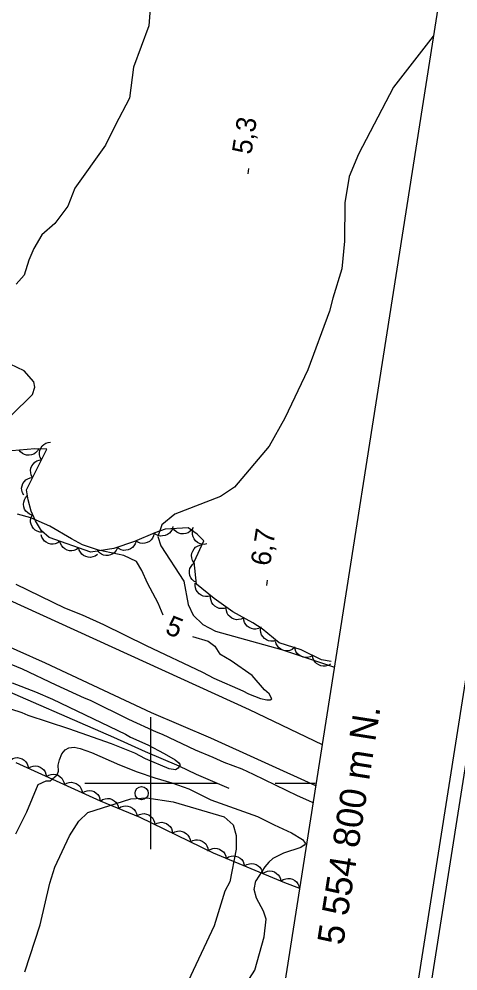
# Model space of a CAD drawing. Extents: x 282461 to 284471, y 5554090 to 5557646.
# Drawn here: x 283980 to 284046.6, y 5554771.5 to 5554915.8 of the extents above; entities that cross this region are included whole.
import ezdxf

# ---------------------------------------------------------------- set-up
doc = ezdxf.new("R2010")
doc.units = 0
for name, color, linetype in [('Niveau 1', 7, 'Continuous'), ('Niveau 2', 7, 'Continuous'), ('Niveau 21', 7, 'Continuous'), ('Niveau 3', 7, 'Continuous'), ('Niveau 36', 7, 'Continuous'), ('Niveau 4', 7, 'Continuous'), ('Niveau 44', 7, 'Continuous'), ('Niveau 60', 7, 'Continuous'), ('Niveau 61', 7, 'Continuous')]:
    doc.layers.add(name, color=color, linetype=linetype)

msp = doc.modelspace()

# ---------------------------------------------------------------- linework, layer by layer
at = {"layer": 'Niveau 1'}
for points in [[(283978.86, 5554855.69), (283982.06, 5554858.86), (283982.41, 5554859.99), (283982.3, 5554860.78), (283980.83, 5554862.48), (283978.67, 5554863.5)], [(284001.9, 5554825.45), (284001.11, 5554827.26), (283999.53, 5554830.31), (283998.63, 5554832.24), (283997.85, 5554833.6), (283995.92, 5554834.51), (283992.06, 5554835.3), (283989.67, 5554836.09), (283987.97, 5554837), (283984.69, 5554838.93), (283981.85, 5554840.18), (283979.81, 5554840.74)], [(283979.55, 5554830.13), (283986.92, 5554826.56), (283989.59, 5554825.48), (283992.82, 5554824.01), (283999.29, 5554820.83), (284007.85, 5554816.81), (284009.55, 5554815.9), (284013.97, 5554813.98), (284014.82, 5554813.52), (284016.63, 5554812.84), (284017.6, 5554812.62), (284018.11, 5554812.62), (284018.34, 5554812.79), (284017.95, 5554813.52), (284017.27, 5554814.15), (284015.4, 5554816.3)], [(284006.32, 5554822.23), (284008.71, 5554821.49), (284009.74, 5554820.74), (284010.48, 5554819.53)], [(284015.4, 5554816.3), (284012.18, 5554818.51), (284010.48, 5554819.53)], [(283978.81, 5554818.01), (283980.51, 5554817.33), (283985.61, 5554814.89), (283989.92, 5554812.91), (283990.83, 5554812.57), (283996.61, 5554809.68), (284000.81, 5554807.76), (284001.72, 5554807.42), (284006.76, 5554805.04), (284009.43, 5554803.96), (284011.07, 5554803.17), (284013.79, 5554802.15), (284015.55, 5554801.36), (284022.18, 5554798.13), (284023.94, 5554797.39), (284024.59, 5554797.05)], [(283985.82, 5554801.25), (283986, 5554801.82), (283985.95, 5554802.72), (283986.18, 5554803.51), (283986.52, 5554804.42), (283987.04, 5554805.04), (283987.61, 5554805.33), (283988.4, 5554805.44), (283989.31, 5554805.27), (283991.02, 5554804.65), (283995.27, 5554802.78), (283997.93, 5554801.7), (284000.6, 5554800.79), (284003.21, 5554800.06), (284005.77, 5554799.15), (284009.11, 5554797.45), (284016.2, 5554794.96), (284018.69, 5554793.66), (284021.36, 5554792.47), (284023, 5554791.45), (284023.45, 5554790.88), (284023.28, 5554790.6), (284022.77, 5554790.26), (284020.15, 5554789.41), (284018.5, 5554788.56), (284017.93, 5554788.05), (284017.3, 5554787.32), (284015.92, 5554785.22)], [(283979.53, 5554792.3), (283981.24, 5554795.64), (283982.92, 5554799.81), (283984.17, 5554800.35), (283984.74, 5554800.35), (283985.82, 5554801.25)], [(284014.17, 5554769.14), (284015.76, 5554771.65), (284017.2, 5554776.72), (284017.48, 5554779.41), (284017.09, 5554780.58), (284016.02, 5554782.56), (284015.69, 5554783.87), (284015.92, 5554785.22)]]:
    msp.add_lwpolyline(points, dxfattribs=at)
at = {"layer": 'Niveau 2'}
for points in [[(284000.07, 5554919.32), (283999.7, 5554914.76), (283997.37, 5554908.47), (283996.78, 5554903.76), (283994.61, 5554899.65), (283993.14, 5554896.66), (283988.51, 5554890.13), (283987.42, 5554887.42), (283985.48, 5554884.81), (283983.48, 5554883.06), (283982.3, 5554881.02), (283981.51, 5554879.25), (283980.82, 5554876.98), (283979.58, 5554875.62)], [(284042.82, 5554913.19), (284036.81, 5554905.43), (284031.48, 5554895.31), (284030.09, 5554891.93), (284029.45, 5554887.94), (284029.4, 5554882.13), (284028.96, 5554877.9), (284027.59, 5554873.5), (284027.09, 5554871.53), (284023.84, 5554862.6), (284020.31, 5554855.28), (284017.95, 5554851.06), (284012.68, 5554844.83), (284010.57, 5554843.43), (284003.67, 5554840.74), (284001.7, 5554839.16), (284001.08, 5554837.38), (284001.55, 5554835.93), (284005, 5554830.62), (284005.67, 5554827.09), (284006.44, 5554825.44), (284007.92, 5554824.01), (284009.81, 5554823.04), (284019.82, 5554820.26), (284027.7, 5554817.62)], [(283979.02, 5554815.19), (283982.54, 5554813.83), (283985.09, 5554812.7), (283996.16, 5554807.42), (283996.95, 5554806.97), (283999.56, 5554805.78), (284002.06, 5554804.48), (284003.71, 5554803.51), (284004.27, 5554803.06), (284004.44, 5554802.77), (284004.15, 5554802.27), (284003.75, 5554802.04), (284002.79, 5554802.15), (283999.21, 5554803.68), (283997.57, 5554804.53), (283994.05, 5554805.95), (283987.57, 5554808.22), (283981.44, 5554810.26), (283980.53, 5554810.66), (283978.77, 5554811.23)], [(283980.93, 5554771.4), (283983.24, 5554778.55), (283984.7, 5554784.83), (283985.44, 5554787.27), (283987.71, 5554792.04), (283989.11, 5554794.25), (283990.49, 5554795.56), (283996.96, 5554797.63), (283999.39, 5554797.77), (284003.4, 5554797.16), (284011.12, 5554794.92), (284012.49, 5554793.68), (284012.93, 5554792.07), (284012.94, 5554790.02), (284012, 5554785.05), (284011.26, 5554783.61), (284009.61, 5554778.4), (284005.26, 5554769.15)]]:
    msp.add_lwpolyline(points, dxfattribs=at)
at = {"layer": 'Niveau 21'}
for points in [[(283896.54, 5554865.24), (283906.59, 5554860.53), (283913.91, 5554857.24), (283921.63, 5554853.44), (283936.73, 5554846.7), (283965.15, 5554833.84), (284014.91, 5554811.14), (284025.97, 5554805.86)], [(283894.01, 5554859.02), (283904.79, 5554853.98), (283912.17, 5554850.4), (283922.9, 5554845.36), (283944.86, 5554835.61), (283957.34, 5554830.35), (283975.37, 5554822.08), (283983.99, 5554818.23), (284000.08, 5554810.69), (284009.04, 5554806.84), (284024.99, 5554799.62)]]:
    msp.add_lwpolyline(points, dxfattribs=at)
at = {"layer": 'Niveau 3'}
for p, q in [((284014.77, 5554892.31), (284014.89, 5554893.1)), ((284017.6, 5554829.95), (284017.72, 5554830.74))]:
    msp.add_line(p, q, dxfattribs=at)
at = {"layer": 'Niveau 36'}
msp.add_circle((283998.62, 5554798.47), 1, dxfattribs=at)
at = {"layer": 'Niveau 4'}
msp.add_lwpolyline([(284011.88, 5554799.19), (284006.96, 5554801.33), (284004.33, 5554802.58), (283999.23, 5554804.74), (283994.41, 5554806.94), (283975.11, 5554815.3), (283970.63, 5554817.46), (283966.48, 5554819.28), (283961.71, 5554821.77), (283949.61, 5554827.73), (283940.34, 5554830.8), (283934.37, 5554832.66), (283930.62, 5554833.73), (283928.8, 5554834.06), (283926.46, 5554833.89), (283925.09, 5554833.7)], dxfattribs=at)
at = {"layer": 'Niveau 44'}
for points in [[(284027.38, 5554818.45), (284025.9, 5554818.69), (284022.8, 5554820.2), (284019.46, 5554821.28), (284016.88, 5554823.37), (284015.48, 5554824.29), (284012.45, 5554825.93), (284009.61, 5554827.99), (284006.94, 5554830.15), (284006.59, 5554833.53), (284008.06, 5554836.7), (284007.06, 5554837.71), (284005.69, 5554838.7), (284002.18, 5554838.46), (284000.62, 5554837.94), (283997.55, 5554836.61), (283994.42, 5554835.55), (283990.93, 5554835), (283984.62, 5554837.21), (283983.45, 5554838.25), (283982.53, 5554839.74), (283981.87, 5554841.22), (283981.42, 5554842.91), (283981.15, 5554844.42), (283984.25, 5554850.59), (283982.43, 5554850.65), (283978.93, 5554850.37)], [(283983.04, 5554850.7), (283982.83, 5554850.33), (283982.54, 5554850.05), (283982.27, 5554849.86), (283981.94, 5554849.74), (283981.57, 5554849.68), (283981.19, 5554849.71), (283980.87, 5554849.78), (283980.56, 5554849.95), (283980.26, 5554850.18), (283980.04, 5554850.46)], [(283983.44, 5554848.98), (283983.24, 5554849.35), (283983.15, 5554849.75), (283983.12, 5554850.08), (283983.2, 5554850.42), (283983.33, 5554850.77), (283983.56, 5554851.08), (283983.78, 5554851.32), (283984.09, 5554851.49), (283984.44, 5554851.63), (283984.79, 5554851.67)], [(283982.09, 5554846.29), (283981.89, 5554846.66), (283981.8, 5554847.06), (283981.77, 5554847.39), (283981.85, 5554847.73), (283981.98, 5554848.08), (283982.21, 5554848.39), (283982.43, 5554848.63), (283982.74, 5554848.81), (283983.08, 5554848.94), (283983.44, 5554848.98)], [(283980.74, 5554843.61), (283980.54, 5554843.97), (283980.45, 5554844.37), (283980.42, 5554844.7), (283980.49, 5554845.05), (283980.63, 5554845.39), (283980.86, 5554845.7), (283981.08, 5554845.94), (283981.39, 5554846.12), (283981.73, 5554846.25), (283982.09, 5554846.29)], [(283982.03, 5554840.6), (283981.64, 5554840.74), (283981.31, 5554840.98), (283981.07, 5554841.21), (283980.89, 5554841.52), (283980.77, 5554841.87), (283980.73, 5554842.25), (283980.74, 5554842.58), (283980.85, 5554842.91), (283981.02, 5554843.24), (283981.26, 5554843.51)], [(283983.59, 5554838.02), (283983.18, 5554838.03), (283982.79, 5554838.17), (283982.5, 5554838.32), (283982.24, 5554838.56), (283982.02, 5554838.86), (283981.87, 5554839.22), (283981.78, 5554839.53), (283981.79, 5554839.88), (283981.87, 5554840.25), (283982.01, 5554840.58)], [(283986.24, 5554836.64), (283985.9, 5554836.39), (283985.52, 5554836.25), (283985.2, 5554836.19), (283984.85, 5554836.21), (283984.49, 5554836.3), (283984.15, 5554836.49), (283983.88, 5554836.68), (283983.67, 5554836.96), (283983.49, 5554837.29), (283983.4, 5554837.64)], [(284000.52, 5554837.9), (284000.44, 5554837.49), (284000.26, 5554837.12), (284000.06, 5554836.85), (283999.79, 5554836.63), (283999.46, 5554836.46), (283999.09, 5554836.37), (283998.76, 5554836.32), (283998.42, 5554836.38), (283998.07, 5554836.51), (283997.76, 5554836.7)], [(284003.37, 5554838.86), (284003.26, 5554838.45), (284003.04, 5554838.11), (284002.83, 5554837.86), (284002.53, 5554837.66), (284002.19, 5554837.52), (284001.81, 5554837.46), (284001.48, 5554837.44), (284001.14, 5554837.53), (284000.8, 5554837.69), (284000.52, 5554837.91)], [(284006.44, 5554838.75), (284006.23, 5554838.39), (284005.93, 5554838.11), (284005.66, 5554837.92), (284005.32, 5554837.81), (284004.96, 5554837.75), (284004.57, 5554837.79), (284004.25, 5554837.85), (284003.95, 5554838.03), (284003.66, 5554838.26), (284003.43, 5554838.55)], [(284008.51, 5554836.24), (284008.1, 5554836.16), (284007.7, 5554836.21), (284007.38, 5554836.29), (284007.07, 5554836.47), (284006.79, 5554836.71), (284006.57, 5554837.02), (284006.41, 5554837.31), (284006.34, 5554837.65), (284006.33, 5554838.03), (284006.4, 5554838.38)], [(283989.08, 5554835.65), (283988.74, 5554835.4), (283988.36, 5554835.26), (283988.04, 5554835.19), (283987.68, 5554835.22), (283987.33, 5554835.31), (283986.99, 5554835.5), (283986.72, 5554835.68), (283986.51, 5554835.96), (283986.33, 5554836.29), (283986.24, 5554836.64)], [(283997.77, 5554836.68), (283997.66, 5554836.28), (283997.44, 5554835.93), (283997.23, 5554835.68), (283996.93, 5554835.49), (283996.59, 5554835.34), (283996.21, 5554835.28), (283995.89, 5554835.26), (283995.54, 5554835.35), (283995.21, 5554835.5), (283994.92, 5554835.72)], [(283991.92, 5554834.65), (283991.58, 5554834.4), (283991.2, 5554834.27), (283990.88, 5554834.2), (283990.52, 5554834.22), (283990.17, 5554834.32), (283989.83, 5554834.5), (283989.56, 5554834.69), (283989.35, 5554834.97), (283989.17, 5554835.3), (283989.08, 5554835.65)], [(283994.94, 5554835.63), (283994.76, 5554835.25), (283994.49, 5554834.95), (283994.24, 5554834.74), (283993.91, 5554834.59), (283993.55, 5554834.5), (283993.17, 5554834.51), (283992.84, 5554834.55), (283992.52, 5554834.69), (283992.21, 5554834.9), (283991.97, 5554835.16)], [(284006.52, 5554833.39), (284006.31, 5554833.74), (284006.21, 5554834.14), (284006.17, 5554834.47), (284006.23, 5554834.82), (284006.36, 5554835.16), (284006.58, 5554835.48), (284006.79, 5554835.73), (284007.09, 5554835.92), (284007.43, 5554836.06), (284007.79, 5554836.11)], [(284006.92, 5554830.38), (284006.55, 5554830.58), (284006.26, 5554830.86), (284006.06, 5554831.13), (284005.93, 5554831.46), (284005.86, 5554831.82), (284005.89, 5554832.21), (284005.94, 5554832.53), (284006.11, 5554832.84), (284006.33, 5554833.14), (284006.61, 5554833.37)], [(284009.1, 5554828.4), (284008.7, 5554828.28), (284008.29, 5554828.28), (284007.96, 5554828.32), (284007.64, 5554828.47), (284007.33, 5554828.67), (284007.08, 5554828.96), (284006.89, 5554829.23), (284006.78, 5554829.57), (284006.73, 5554829.93), (284006.76, 5554830.29)], [(284011.52, 5554826.61), (284011.12, 5554826.46), (284010.71, 5554826.44), (284010.38, 5554826.47), (284010.06, 5554826.6), (284009.74, 5554826.79), (284009.47, 5554827.06), (284009.27, 5554827.32), (284009.14, 5554827.65), (284009.07, 5554828.01), (284009.08, 5554828.37)], [(284014.08, 5554825.05), (284013.71, 5554824.85), (284013.31, 5554824.78), (284012.98, 5554824.76), (284012.63, 5554824.84), (284012.29, 5554824.99), (284011.99, 5554825.23), (284011.76, 5554825.46), (284011.59, 5554825.77), (284011.47, 5554826.12), (284011.43, 5554826.48)], [(284016.73, 5554823.62), (284016.36, 5554823.42), (284015.95, 5554823.35), (284015.62, 5554823.33), (284015.28, 5554823.41), (284014.94, 5554823.56), (284014.64, 5554823.8), (284014.4, 5554824.02), (284014.24, 5554824.34), (284014.12, 5554824.69), (284014.08, 5554825.05)], [(284019.02, 5554821.64), (284018.62, 5554821.52), (284018.21, 5554821.52), (284017.88, 5554821.56), (284017.56, 5554821.7), (284017.25, 5554821.91), (284017, 5554822.2), (284016.81, 5554822.47), (284016.7, 5554822.8), (284016.65, 5554823.17), (284016.68, 5554823.53)], [(284021.78, 5554820.53), (284021.45, 5554820.27), (284021.07, 5554820.12), (284020.75, 5554820.05), (284020.4, 5554820.07), (284020.04, 5554820.15), (284019.69, 5554820.33), (284019.42, 5554820.51), (284019.2, 5554820.78), (284019.02, 5554821.11), (284018.92, 5554821.46)], [(284024.54, 5554819.35), (284024.18, 5554819.14), (284023.78, 5554819.05), (284023.45, 5554819.02), (284023.11, 5554819.09), (284022.76, 5554819.22), (284022.45, 5554819.44), (284022.2, 5554819.66), (284022.02, 5554819.96), (284021.89, 5554820.31), (284021.84, 5554820.67)], [(284027.25, 5554818.03), (284026.88, 5554817.82), (284026.49, 5554817.73), (284026.16, 5554817.7), (284025.81, 5554817.77), (284025.47, 5554817.9), (284025.15, 5554818.13), (284024.91, 5554818.34), (284024.73, 5554818.65), (284024.59, 5554818.99), (284024.54, 5554819.35)], [(283978.72, 5554803.5), (283979.08, 5554803.71), (283979.47, 5554803.82), (283979.8, 5554803.86), (283980.15, 5554803.8), (283980.49, 5554803.67), (283980.81, 5554803.46), (283981.06, 5554803.25), (283981.25, 5554802.95), (283981.39, 5554802.61), (283981.45, 5554802.25)], [(283979.55, 5554803.12), (283992.32, 5554797.31), (283998.36, 5554794.85), (284009.45, 5554789.42), (284020.29, 5554784.93), (284022.55, 5554784.07)], [(283981.45, 5554802.25), (283981.81, 5554802.47), (283982.2, 5554802.57), (283982.53, 5554802.61), (283982.87, 5554802.56), (283983.22, 5554802.43), (283983.54, 5554802.22), (283983.79, 5554802.01), (283983.98, 5554801.71), (283984.12, 5554801.37), (283984.18, 5554801.01)], [(283984.18, 5554801.01), (283984.54, 5554801.23), (283984.93, 5554801.33), (283985.26, 5554801.37), (283985.6, 5554801.31), (283985.95, 5554801.19), (283986.27, 5554800.98), (283986.52, 5554800.77), (283986.7, 5554800.47), (283986.85, 5554800.13), (283986.91, 5554799.77)], [(283986.91, 5554799.77), (283987.26, 5554799.99), (283987.66, 5554800.09), (283987.98, 5554800.13), (283988.33, 5554800.07), (283988.68, 5554799.95), (283989, 5554799.74), (283989.25, 5554799.53), (283989.43, 5554799.23), (283989.58, 5554798.89), (283989.64, 5554798.53)], [(283989.64, 5554798.53), (283989.99, 5554798.75), (283990.39, 5554798.85), (283990.71, 5554798.89), (283991.06, 5554798.83), (283991.41, 5554798.71), (283991.72, 5554798.49), (283991.97, 5554798.28), (283992.16, 5554797.99), (283992.3, 5554797.64), (283992.36, 5554797.29)], [(283992.37, 5554797.29), (283992.71, 5554797.52), (283993.1, 5554797.64), (283993.43, 5554797.69), (283993.78, 5554797.65), (283994.13, 5554797.54), (283994.45, 5554797.34), (283994.71, 5554797.14), (283994.91, 5554796.85), (283995.07, 5554796.51), (283995.14, 5554796.16)], [(283995.14, 5554796.16), (283995.49, 5554796.39), (283995.88, 5554796.51), (283996.2, 5554796.56), (283996.55, 5554796.52), (283996.9, 5554796.41), (283997.23, 5554796.21), (283997.49, 5554796.01), (283997.69, 5554795.72), (283997.84, 5554795.38), (283997.92, 5554795.03)], [(283997.93, 5554795.06), (283998.29, 5554795.27), (283998.69, 5554795.36), (283999.02, 5554795.39), (283999.36, 5554795.32), (283999.71, 5554795.19), (284000.02, 5554794.96), (284000.26, 5554794.75), (284000.44, 5554794.44), (284000.57, 5554794.1), (284000.62, 5554793.74)], [(284000.62, 5554793.74), (284000.98, 5554793.95), (284001.38, 5554794.04), (284001.71, 5554794.07), (284002.05, 5554794), (284002.4, 5554793.87), (284002.71, 5554793.65), (284002.95, 5554793.43), (284003.13, 5554793.13), (284003.26, 5554792.78), (284003.31, 5554792.42)], [(284003.31, 5554792.42), (284003.68, 5554792.63), (284004.07, 5554792.72), (284004.4, 5554792.75), (284004.75, 5554792.68), (284005.09, 5554792.55), (284005.4, 5554792.33), (284005.64, 5554792.11), (284005.82, 5554791.81), (284005.96, 5554791.46), (284006.01, 5554791.11)], [(284006.01, 5554791.11), (284006.37, 5554791.31), (284006.77, 5554791.4), (284007.09, 5554791.43), (284007.44, 5554791.37), (284007.78, 5554791.23), (284008.09, 5554791.01), (284008.34, 5554790.79), (284008.52, 5554790.49), (284008.65, 5554790.14), (284008.7, 5554789.79)], [(284008.68, 5554789.74), (284009.03, 5554789.97), (284009.42, 5554790.09), (284009.74, 5554790.14), (284010.09, 5554790.09), (284010.44, 5554789.98), (284010.77, 5554789.77), (284011.02, 5554789.57), (284011.22, 5554789.28), (284011.37, 5554788.95), (284011.45, 5554788.59)], [(284011.45, 5554788.59), (284011.8, 5554788.82), (284012.18, 5554788.94), (284012.51, 5554788.99), (284012.86, 5554788.94), (284013.21, 5554788.83), (284013.54, 5554788.63), (284013.79, 5554788.43), (284013.99, 5554788.13), (284014.14, 5554787.8), (284014.22, 5554787.45)], [(284014.22, 5554787.45), (284014.56, 5554787.68), (284014.95, 5554787.79), (284015.28, 5554787.84), (284015.63, 5554787.8), (284015.98, 5554787.68), (284016.3, 5554787.48), (284016.56, 5554787.28), (284016.76, 5554786.99), (284016.91, 5554786.65), (284016.99, 5554786.3)], [(284016.99, 5554786.3), (284017.33, 5554786.53), (284017.72, 5554786.64), (284018.05, 5554786.7), (284018.4, 5554786.65), (284018.75, 5554786.54), (284019.07, 5554786.33), (284019.33, 5554786.13), (284019.53, 5554785.84), (284019.68, 5554785.5), (284019.75, 5554785.15)], [(284019.75, 5554785.14), (284020.09, 5554785.38), (284020.48, 5554785.5), (284020.8, 5554785.56), (284021.15, 5554785.53), (284021.51, 5554785.43), (284021.84, 5554785.23), (284022.1, 5554785.04), (284022.3, 5554784.75), (284022.47, 5554784.42), (284022.55, 5554784.07)]]:
    msp.add_lwpolyline(points, dxfattribs=at)
at = {"layer": 'Niveau 60'}
for points in [[(283935.57, 5554089.71), (284458.46, 5557413.53), (282983.71, 5557645.53), (282460.81, 5554321.72), (283935.57, 5554089.71)], [(283933.91, 5554092), (284456.17, 5557411.87), (282985.38, 5557643.25), (282463.1, 5554323.39), (283933.91, 5554092)], [(282485.97, 5554340.04), (282921.22, 5557106.72), (284352.51, 5556881.56), (283917.27, 5554114.87), (282485.97, 5554340.04)]]:
    msp.add_lwpolyline(points, dxfattribs=at)
at = {"layer": 'Niveau 61'}
for points in [[(284000, 5554790), (284000, 5554810)], [(283990, 5554800), (284010, 5554800)], [(284018.88, 5554800), (284024.95, 5554800)]]:
    msp.add_lwpolyline(points, dxfattribs=at)

# ---------------------------------------------------------------- texts
at = {"layer": 'Niveau 1'}
msp.add_text('5', height=3, rotation=337.8337, dxfattribs=at).set_placement((284002.03, 5554822.74))
at = {"layer": 'Niveau 3'}
for s, p in [('5,3  ', (284015.25, 5554895.15)), ('6,7  ', (284018.08, 5554832.79))]:
    msp.add_text(s, height=3, rotation=81.0957, dxfattribs=at).set_placement(p)
at = {"layer": 'Niveau 61'}
msp.add_text('5 554 800 m N.', height=4, rotation=81.0596, dxfattribs=at).set_placement((284029.17, 5554775.34))

doc.saveas('drawing.dxf')
